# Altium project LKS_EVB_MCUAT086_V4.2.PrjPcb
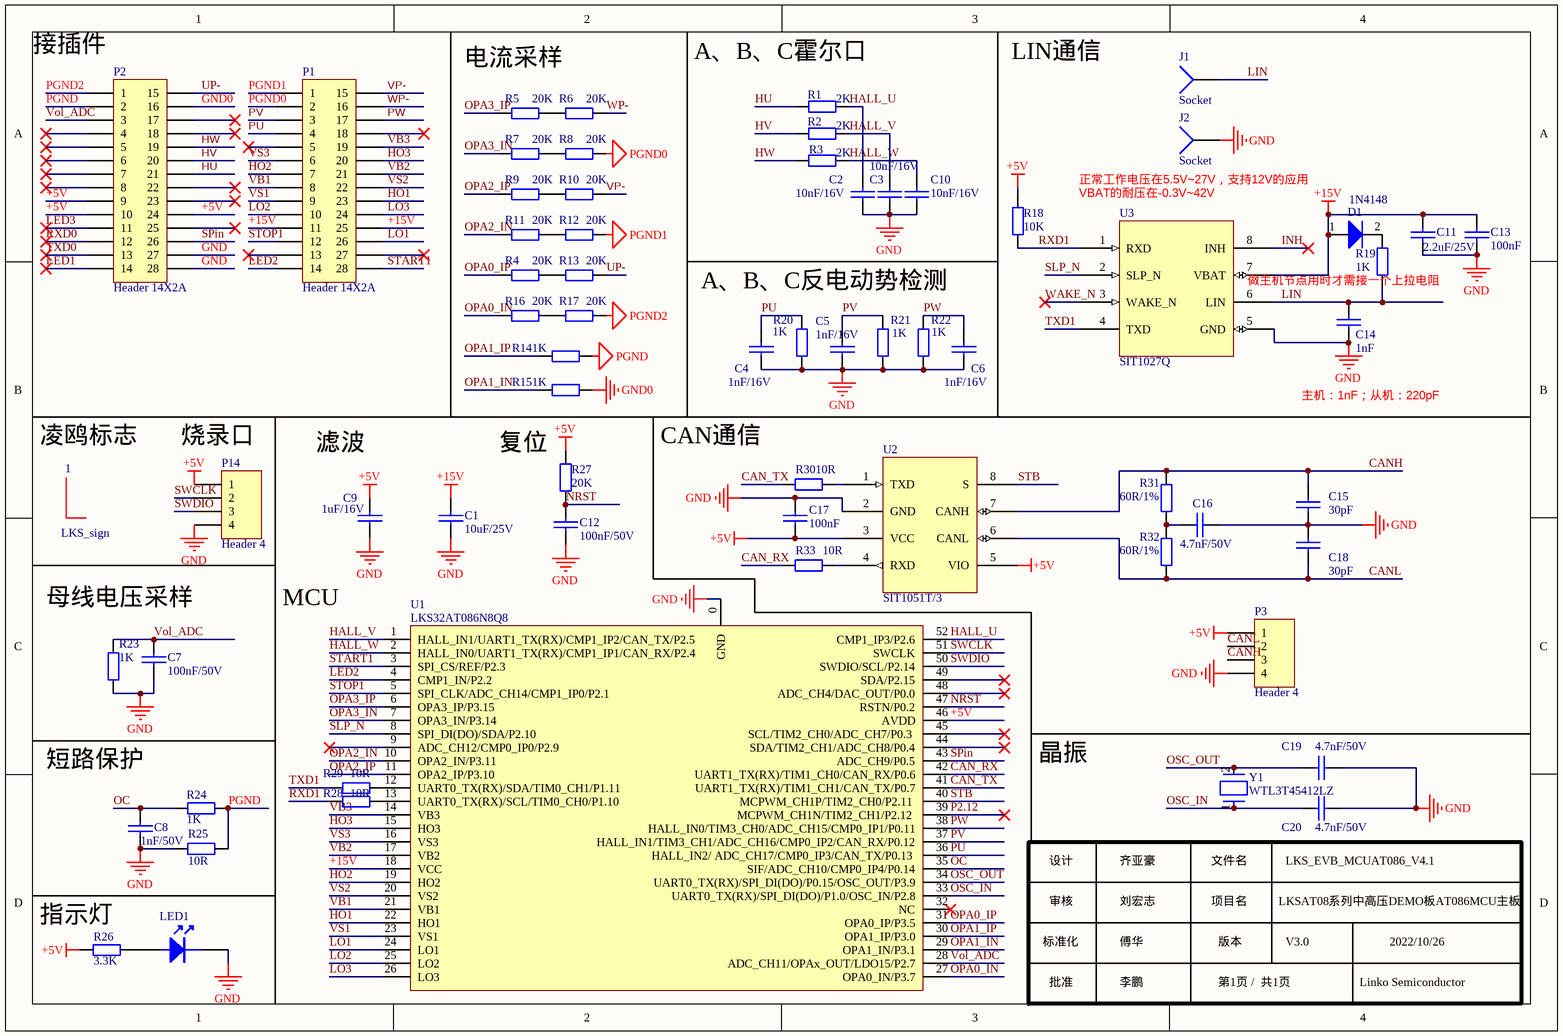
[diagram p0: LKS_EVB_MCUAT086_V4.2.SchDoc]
1 sheet, 66 parts. Net scope: global (net labels, ports and power ports of the same name join across sheets).
Board file: LKS_EVB_MCUAT086_V4.2.PcbDoc

## Sheet LKS_EVB_MCUAT086_V4.2.SchDoc
size A4; SheetNumber: 1; SheetTotal: 1

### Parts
1  LKS_sign  [LKS_LOGO2]
C1  10uF/25V  [0805C]
C2  10nF/16V  [0603C]
C3  10nF/16V  [0603C]
C4  1nF/16V  [0603C]
C5  1nF/16V  [0603C]
C6  1nF/16V  [0603C]
C7  100nF/50V  [0603C]
C8  1nF/50V  [0603C]
C9  1uF/16V  [0603C]
C10  10nF/16V  [0603C]
C11  2.2uF/25V  [0603C _1]
C12  100nF/50V  [0603C]
C13  100nF  [0603C _1]
C14  1nF  [0805C]
C15  30pF  [0603C _1]
C16  4.7nF/50V  [0603C _1]
C17  100nF  [0603C _1]
C18  30pF  [0603C _1]
C19  4.7nF/50V  [0603C _1]
C20  4.7nF/50V  [0603C _1]
D1  1N4148  [SOD123]
J1  Socket  [PIN1]
J2  Socket  [PIN1]
LED1  LED  [0603D]  (value not drawn)
P1  Header 14X2A  [HDR2 2X14 底层]
P2  Header 14X2A  [HDR2 2X14 底层]
P3  Header 4  [HDR1X4]
P14  Header 4  [HDR 1X4]
R1  2K  [0603R]
R2  2K  [0603R]
R3  2K  [0603R]
R4  20K  [0603R]
R5  20K  [0603R]
R6  20K  [0603R]
R7  20K  [0603R]
R8  20K  [0603R]
R9  20K  [0603R]
R10  20K  [0603R]
R11  20K  [0603R]
R12  20K  [0603R]
R13  20K  [0603R]
R14  1K  [0603R]
R15  1K  [0603R]
R16  20K  [0603R]
R17  20K  [0603R]
R18  10K  [0603R_1]
R19  1K  [0603R_1]
R20  1K  [0603R]
R21  1K  [0603R]
R22  1K  [0603R]
R23  1K  [0603R]
R24  1K  [0603R]
R25  10R  [0603R]
R26  3.3K  [0603R]
R27  20K  [0603R]
R28  10R  [0603R]
R29  10R  [0603R]
R30  10R  [0603R_1]
R31  60R/1%  [0603R_1]
R32  60R/1%  [0603R_1]
R33  10R  [0603R_1]
U1  LKS32AT086N8Q8  [QFN52]
U2  SIT1051T/3  [SOP-8N]
U3  SIT1027Q  [SOP-8N]
Y1  WTL3T45412LZ  [DT-38]

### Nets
+5V: C9.2 C17.2 P2.9 P2.10 P2.24 P3.1 P14.1 R18.1 R26.2 R27.1 U1.46(AVDD) U2.3(VCC) U2.5(VIO)
+15V: C1.1 C11.1 C13.1 D1.1(A) P1.11 P1.25 U1.18(VCC) U3.7(VBAT)
GND: C1.2 C2.2 C3.2 C4.2 C5.2 C6.2 C7.1 C8.1 C9.1 C10.2 C11.2 C12.2 C13.2 C14.2 C15.2 C16.2 C17.1 C18.1 C19.2 C20.2 J2.1 LED1.2(K) P2.27 P2.28 P3.4 P14.4 R20.2 R21.2 R22.2 R23.1 R25.2 U1.0(GND) U2.2(GND) U3.5(GND)
GND0: P2.16 R15.1
PGND: P2.2 R14.1 R24.2 R25.1
PGND0: P1.2 R8.1
PGND1: P1.1 R12.1
PGND2: P2.1 R17.1
CAN_RX: R33.1 U1.42(UART1_TX(RX)/TIM1_CH0/CAN_RX/P0.6)
CAN_TX: R30.1 U1.41(UART1_TX(RX)/TIM1_CH1/CAN_TX/P0.7)
CANH: C15.1 P3.3 R31.1 U2.7(CANH)
CANL: C18.2 P3.2 R32.2 U2.6(CANL)
HALL_U: C2.1 R1.2 U1.52(CMP1_IP3/P2.6)
HALL_V: C3.1 R2.2 U1.1(HALL_IN1/UART1_TX(RX)/CMP1_IP2/CAN_TX/P2.5)
HALL_W: C10.1 R3.2 U1.2(HALL_IN0/UART1_TX(RX)/CMP1_IP1/CAN_RX/P2.4)
HO1: P1.23 U1.22(HO1)
HO2: P1.7 U1.19(HO2)
HO3: P1.20 U1.15(HO3)
HU: P2.21 R1.1
HV: P2.20 R2.1
HW: P2.19 R3.1
INH: U3.8(INH)
LED1: P2.14
LED2: P1.14 U1.4(CMP1_IN/P2.2)
LED3: P2.11
LIN: C14.1 J1.1 R19.2 U3.6(LIN)
LO1: P1.26 U1.24(LO1)
LO2: P1.10 U1.25(LO2)
LO3: P1.24 U1.26(LO3)
NRST: C12.1 R27.2 U1.47(RSTN/P0.2)
OC: C8.2 R24.1 U1.35(SIF/ADC_CH10/CMP0_IP4/P0.14)
OPA0_IN: R16.2 U1.27(OPA0_IN/P3.7)
OPA0_IP: R4.2 U1.31(OPA0_IP/P3.5)
OPA1_IN: R15.2 U1.29(OPA1_IN/P3.1)
OPA1_IP: R14.2 U1.30(OPA1_IP/P3.0)
OPA2_IN: R11.2 U1.10(OPA2_IN/P3.11)
OPA2_IP: R9.2 U1.11(OPA2_IP/P3.10)
OPA3_IN: R7.2 U1.7(OPA3_IN/P3.14)
OPA3_IP: R5.2 U1.6(OPA3_IP/P3.15)
OSC_IN: C20.1 U1.33(UART0_TX(RX)/SPI_DI(DO)/P1.0/OSC_IN/P2.8) Y1.1
OSC_OUT: C19.1 U1.34(UART0_TX(RX)/SPI_DI(DO)/P0.15/OSC_OUT/P3.9) Y1.2
P2.12: U1.39(MCPWM_CH1N/TIM2_CH1/P2.12)
PU: C4.1 P1.4 R20.1 U1.36(HALL_IN2/_ADC_CH17/CMP0_IP3/CAN_TX/P0.13)
PV: C5.1 P1.3 R21.1 U1.37(HALL_IN1/TIM3_CH1/ADC_CH16/CMP0_IP2/CAN_RX/P0.12)
PW: C6.1 P1.17 R22.1 U1.38(HALL_IN0/TIM3_CH0/ADC_CH15/CMP0_IP1/P0.11)
RXD0: P2.12
RXD1: R18.2 R28.1 U3.1(RXD)
SLP_N: U1.8(SPI_DI(DO)/SDA/P2.10) U3.2(SLP_N)
SPin: P2.26 U1.43(ADC_CH9/P0.5)
START1: P1.28 U1.3(SPI_CS/REF/P2.3)
STB: U1.40(MCPWM_CH1P/TIM2_CH0/P2.11) U2.8(S)
STOP1: P1.12 U1.5(SPI_CLK/ADC_CH14/CMP1_IP0/P2.1)
SWCLK: P14.2 U1.51(SWCLK)
SWDIO: P14.3 U1.50(SWDIO/SCL/P2.14)
TXD0: P2.13
TXD1: R29.1 U3.4(TXD)
UP-: P2.15 R13.1
VB1: P1.8 U1.21(VB1)
VB2: P1.21 U1.17(VB2)
VB3: P1.19 U1.14(VB3)
Vol_ADC: C7.2 P2.3 R23.2 U1.28(ADC_CH11/OPAx_OUT/LDO15/P2.7)
VP-: P1.15 R10.1
VS1: P1.9 U1.23(VS1)
VS2: P1.22 U1.20(VS2)
VS3: P1.6 U1.16(VS3)
WAKE_N: U3.3(WAKE_N)
WP-: P1.16 R6.1
NetC16_1: C16.1 R31.2 R32.1
NetD1_2: D1.2(K) R19.1
NetLED1_1: LED1.1(A) R26.1
NetR4_1: R4.1 R13.2
NetR5_1: R5.1 R6.2
NetR7_1: R7.1 R8.2
NetR9_1: R9.1 R10.2
NetR11_1: R11.1 R12.2
NetR16_1: R16.1 R17.2
NetR28_2: R28.2 U1.13(UART0_TX(RX)/SCL/TIM0_CH0/P1.10)
NetR29_2: R29.2 U1.12(UART0_TX(RX)/SDA/TIM0_CH1/P1.11)
NetR30_2: R30.2 U2.1(TXD)
NetR33_2: R33.2 U2.4(RXD)

Not connected (* = marked no-connect by the designer): P1 5* 13* 18* 27*; P2 4* 5* 6* 7* 8* 17* 18* 22* 23* 25*; U1 9(ADC_CH12/CMP0_IP0/P2.9)* 32(NC)* 44(SDA/TIM2_CH1/ADC_CH8/P0.4)* 45(SCL/TIM2_CH0/ADC_CH7/P0.3_)* 48(ADC_CH4/DAC_OUT/P0.0)* 49(SDA/P2.15)*

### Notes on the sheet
- 接插件
- A、B、C霍尔口
- LIN通信
- (near J2) 正常工作电压在5.5V|7V，支持12V的应用
- VBAT的耐压在-0.3V~42V
- (near U3) 做主机节点用时才需接一个上拉电阻
- (near 1) 凌鸥标志
- (near P14) 烧录口
- CAN通信
- 主机：1nF；从机：220pF
- 滤波
- 复位
- 母线电压采样
- 短路保护
- 晶振
- (near R26) 指示灯
- 设计
- 审核
- 齐亚豪
- 刘宏志
- 文件名
- 项目名
- LKSAT08系列中高压DEMO板AT086MCU主板
- LKS_EVB_MCUAT086_V4.1
- 标准化
- 批准
- 傅华
- 李鹏
- 版本
- 第1页 /  共1页
- V3.0
- Linko Semiconductor
- 2022/10/26
- Labels drawn without touching a wire or pin: A、B、C反电动势检测, MCU, 电流采样

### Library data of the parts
C1 C11 C13-C20 = Capacitor: Capacitor --贴片电容
C2-C6 C10 = CAP: Capacitor
C7-C9 C12 = C: Capacitor
D1 = Diode: Default Diode
LED1 = LED: LED_Light
P1 P2 = Header 14X2A: Header, 14-Pin, Dual row
P3 P14 = Header 4: Header, 4-Pin
R1-R25 R27-R33 = Res: Resistor; Value: K
R26 = Res: Resistor; Value: 330
U1 = LKS32AT086N8Q8: 车规芯片
U2 = SIT1051T/3: SIT芯力特CAN芯片  sop-8
U3 = SIT1021T: SIT芯力特LIN芯片  SOP-8
Y1 = CMP-27762-006068-1: CRYSTAL 32.7680KHZ 12.5PF TH; Manufacturer: Abracon; Manufacturer Part Number: AB26TRB-32.768KHZ-T; Operating Frequency: 32.768 kHz; Series Resistance: 50kR; Frequency Tolerance: 20ppm; Frequency Stability: -0.034ppm; Frequency: 32.768kHz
